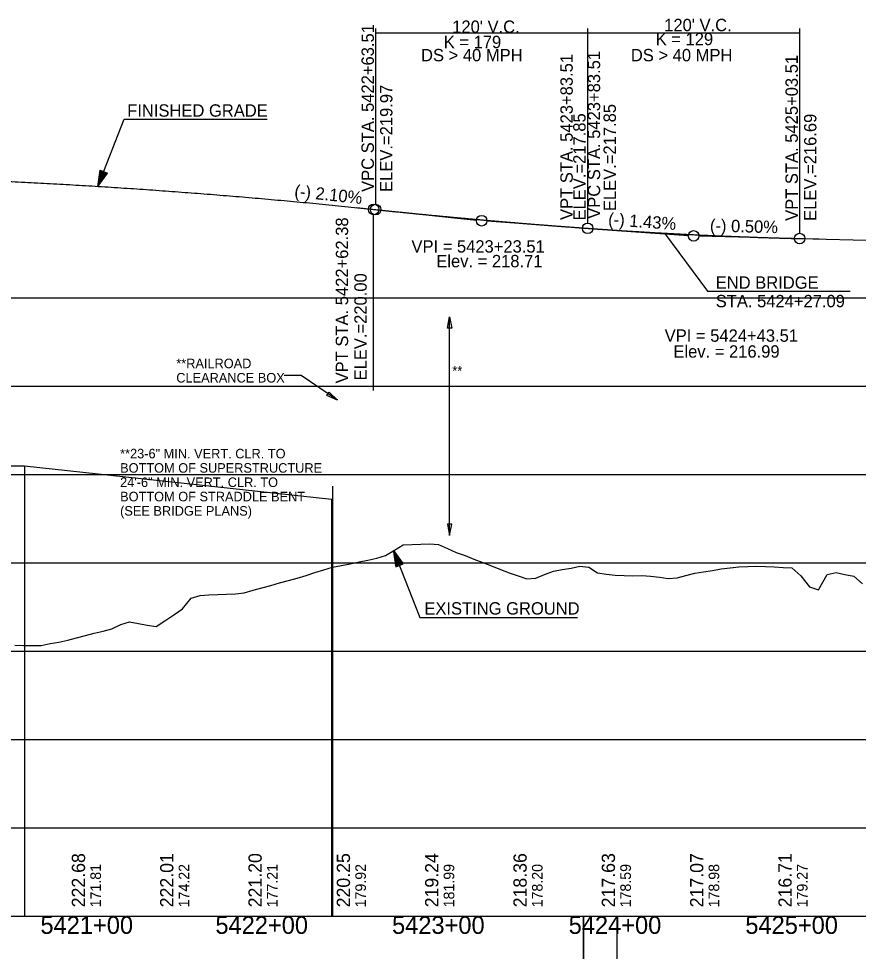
# Model space of a CAD drawing. Extents: x 69 to 2003113, y 512 to 837401.
# Drawn here: x 1885998 to 1886474, y 775969 to 776497 of the extents above; entities that cross this region are included whole.
import ezdxf

# ---------------------------------------------------------------- set-up
doc = ezdxf.new("R2010")
doc.units = 0
for name, color, linetype in [('BR_AUTO DIMENSION', 7, 'Continuous'), ('BR_BORDER LINES', 7, 'Continuous'), ('BR_CENTER LINE BASELINE', 7, 'Continuous'), ('BR_CONCRETE', 7, 'Continuous'), ('BR_GRID DOTS', 7, 'Continuous'), ('BR_GRID LINES', 7, 'Continuous'), ('BR_TEXT', 7, 'Continuous'), ('RD_HC_Points', 7, 'Continuous'), ('RD_PD_ALT1_TrvlWay', 7, 'Continuous'), ('RD_SHT_ID', 7, 'Continuous'), ('RD_SHT_IplotShp', 7, 'Continuous')]:
    doc.layers.add(name, color=color, linetype=linetype)

msp = doc.modelspace()

# ---------------------------------------------------------------- linework, layer by layer
at = {"layer": 'BR_AUTO DIMENSION'}
for p, q in [((1883686.1, 776339.14), (1888825.1, 776339.14)), ((1883686.1, 776289.14), (1888825.1, 776289.14)), ((1885909.13, 776244.04), (1886001.66, 776244.04)), ((1886001.66, 776244.04), (1886001.66, 775989.14)), ((1886001.66, 776244.04), (1886175.45, 776225.04)), ((1883686.1, 776239.14), (1888825.1, 776239.14)), ((1886176.11, 776232.54), (1886176.11, 775989.14)), ((1886175.45, 776225.04), (1886175.45, 775989.14)), ((1886175.45, 776225.04), (1886176.11, 776225.04)), ((1883686.1, 776189.14), (1888825.1, 776189.14)), ((1883686.1, 776139.14), (1888825.1, 776139.14)), ((1883686.1, 776089.14), (1888825.1, 776089.14)), ((1883686.1, 776039.14), (1888825.1, 776039.14)), ((1883636.94, 775989.14), (1888825.1, 775989.14)), ((1886318.05, 775989.14), (1886318.05, 772615.57)), ((1886336.94, 775989.14), (1886336.94, 774739.14))]:
    msp.add_line(p, q, dxfattribs=at)
at = {"layer": 'BR_BORDER LINES'}
for p, q in [((1883686.1, 775989.14), (1889486.1, 775989.14)), ((1886318.05, 774739.14), (1886318.05, 775989.14))]:
    msp.add_line(p, q, dxfattribs=at)
at = {"layer": 'BR_CENTER LINE BASELINE'}
for p, q in [((1886189.84, 776390.11), (1886257.46, 776383.01)), ((1886331.27, 776377.63), (1886263.44, 776382.49)), ((1886336.94, 776377.23), (1886377.46, 776374.33)), ((1886451.43, 776372.33), (1886383.45, 776374.04))]:
    msp.add_line(p, q, dxfattribs=at)
for centre in [(1886260.45, 776382.7), (1886380.45, 776374.11)]:
    msp.add_circle(centre, 3, dxfattribs=at)
at = {"layer": 'BR_GRID DOTS'}
for p, q in [((1886200.45, 776491.5), (1886200.45, 776392)), ((1886320.45, 776491.5), (1886320.45, 776381.41)), ((1886440.45, 776491.5), (1886440.45, 776375.61)), ((1886200.45, 776489), (1886320.45, 776489)), ((1886320.45, 776489), (1886440.45, 776489)), ((1886320.45, 776489), (1886336.94, 776489)), ((1886320.45, 776480.91), (1886320.45, 776381.41)), ((1886199.32, 776286.62), (1886199.32, 776386.12)), ((1885474.32, 776289.12), (1886199.32, 776289.12))]:
    msp.add_line(p, q, dxfattribs=at)
for centre in [(1886199.32, 776389.12), (1886200.45, 776389), (1886320.45, 776378.41), (1886320.45, 776378.41), (1886440.45, 776372.61)]:
    msp.add_circle(centre, 3, dxfattribs=at)
at = {"layer": 'BR_GRID LINES'}
for p, q in [((1886199.32, 776389.12), (1886200.45, 776389)), ((1886320.45, 776378.41), (1886320.45, 776378.41)), ((1886440.45, 776372.61), (1886536.94, 776370.19))]:
    msp.add_line(p, q, dxfattribs=at)
for points in [[(1885474.32, 776392.63), (1885488.82, 776393.99), (1885503.32, 776395.28), (1885517.82, 776396.52), (1885532.32, 776397.7), (1885546.82, 776398.82), (1885561.32, 776399.88), (1885575.82, 776400.88), (1885590.32, 776401.83), (1885604.82, 776402.72), (1885619.32, 776403.55), (1885633.82, 776404.32), (1885648.32, 776405.03), (1885662.82, 776405.69), (1885677.32, 776406.29), (1885691.82, 776406.83), (1885706.32, 776407.31), (1885720.82, 776407.73), (1885735.32, 776408.1), (1885749.82, 776408.41), (1885764.32, 776408.65), (1885778.82, 776408.85), (1885793.32, 776408.98), (1885807.82, 776409.05), (1885822.32, 776409.07), (1885836.82, 776409.03), (1885851.32, 776408.93), (1885865.82, 776408.77), (1885880.32, 776408.56), (1885894.82, 776408.28), (1885909.32, 776407.95), (1885923.82, 776407.56), (1885938.32, 776407.11), (1885952.82, 776406.61), (1885967.32, 776406.04), (1885981.82, 776405.42), (1885996.32, 776404.74), (1886010.82, 776404), (1886025.32, 776403.21), (1886039.82, 776402.35), (1886054.32, 776401.44), (1886068.82, 776400.47), (1886083.32, 776399.44), (1886097.82, 776398.35), (1886112.32, 776397.21), (1886126.82, 776396.01), (1886141.32, 776394.74), (1886155.82, 776393.43), (1886170.32, 776392.05), (1886184.82, 776390.61), (1886199.32, 776389.12)], [(1886200.45, 776389), (1886202.85, 776388.75), (1886205.25, 776388.5), (1886207.65, 776388.25), (1886210.05, 776388.01), (1886212.45, 776387.76), (1886214.85, 776387.52), (1886217.25, 776387.28), (1886219.65, 776387.04), (1886222.05, 776386.8), (1886224.45, 776386.56), (1886226.85, 776386.33), (1886229.25, 776386.09), (1886231.65, 776385.86), (1886234.05, 776385.63), (1886236.45, 776385.4), (1886238.85, 776385.17), (1886241.25, 776384.95), (1886243.65, 776384.72), (1886246.05, 776384.5), (1886248.45, 776384.28), (1886250.85, 776384.06), (1886253.25, 776383.84), (1886255.65, 776383.63), (1886258.05, 776383.41), (1886260.45, 776383.2), (1886262.85, 776382.99), (1886265.25, 776382.78), (1886267.65, 776382.57), (1886270.05, 776382.37), (1886272.45, 776382.16), (1886274.85, 776381.96), (1886277.25, 776381.76), (1886279.65, 776381.56), (1886282.05, 776381.36), (1886284.45, 776381.16), (1886286.85, 776380.97), (1886289.25, 776380.77), (1886291.65, 776380.58), (1886294.05, 776380.39), (1886296.45, 776380.2), (1886298.85, 776380.02), (1886301.25, 776379.83), (1886303.65, 776379.65), (1886306.05, 776379.47), (1886308.45, 776379.29), (1886310.85, 776379.11), (1886313.25, 776378.93), (1886315.65, 776378.75), (1886318.05, 776378.58), (1886320.45, 776378.41)], [(1886320.45, 776378.41), (1886320.78, 776378.38), (1886321.11, 776378.36), (1886321.44, 776378.34), (1886321.77, 776378.31), (1886322.1, 776378.29), (1886322.43, 776378.27), (1886322.76, 776378.24), (1886323.09, 776378.22), (1886323.42, 776378.2), (1886323.75, 776378.17), (1886324.08, 776378.15), (1886324.41, 776378.13), (1886324.74, 776378.1), (1886325.07, 776378.08), (1886325.4, 776378.06), (1886325.73, 776378.03), (1886326.06, 776378.01), (1886326.38, 776377.99), (1886326.71, 776377.97), (1886327.04, 776377.94), (1886327.37, 776377.92), (1886327.7, 776377.9), (1886328.03, 776377.87), (1886328.36, 776377.85), (1886328.69, 776377.83), (1886329.02, 776377.81), (1886329.35, 776377.78), (1886329.68, 776377.76), (1886330.01, 776377.74), (1886330.34, 776377.72), (1886330.67, 776377.7), (1886331, 776377.67), (1886331.33, 776377.65), (1886331.66, 776377.63), (1886331.99, 776377.61), (1886332.32, 776377.58), (1886332.65, 776377.56), (1886332.98, 776377.54), (1886333.31, 776377.52), (1886333.64, 776377.5), (1886333.97, 776377.47), (1886334.3, 776377.45), (1886334.63, 776377.43), (1886334.96, 776377.41), (1886335.29, 776377.39), (1886335.62, 776377.37), (1886335.95, 776377.34), (1886336.28, 776377.32), (1886336.61, 776377.3), (1886336.94, 776377.28)], [(1886336.94, 776377.28), (1886337.25, 776377.26), (1886339.65, 776377.1), (1886342.05, 776376.95), (1886344.45, 776376.8), (1886346.85, 776376.65), (1886349.25, 776376.51), (1886351.65, 776376.36), (1886354.05, 776376.22), (1886356.45, 776376.08), (1886358.85, 776375.94), (1886361.25, 776375.81), (1886363.65, 776375.68), (1886366.05, 776375.55), (1886368.45, 776375.42), (1886370.85, 776375.29), (1886373.25, 776375.17), (1886375.65, 776375.05), (1886378.05, 776374.93), (1886380.45, 776374.81), (1886382.85, 776374.7), (1886385.25, 776374.58), (1886387.65, 776374.47), (1886390.05, 776374.36), (1886392.45, 776374.26), (1886394.85, 776374.15), (1886397.25, 776374.05), (1886399.65, 776373.95), (1886402.05, 776373.86), (1886404.45, 776373.76), (1886406.85, 776373.67), (1886409.25, 776373.58), (1886411.65, 776373.49), (1886414.05, 776373.41), (1886416.45, 776373.32), (1886418.85, 776373.24), (1886421.25, 776373.16), (1886423.65, 776373.08), (1886426.05, 776373.01), (1886428.45, 776372.94), (1886430.85, 776372.87), (1886433.25, 776372.8), (1886435.65, 776372.73), (1886438.05, 776372.67), (1886440.45, 776372.61)]]:
    msp.add_spline(points, degree=3, dxfattribs=at)
at = {"layer": 'BR_TEXT'}
for points in [[(1886186.1, 776188.56), (1886191.1, 776189.59), (1886196.1, 776190.66), (1886201.1, 776191.75), (1886206.1, 776193.28), (1886211.1, 776196.36), (1886216.1, 776199.38), (1886221.1, 776199.52), (1886226.1, 776199.65), (1886231.1, 776199.78), (1886236.1, 776199.5), (1886241.1, 776197.2), (1886246.1, 776195), (1886251.1, 776193.18), (1886256.1, 776191.23), (1886261.1, 776189.28), (1886266.1, 776187.34), (1886271.1, 776185.4), (1886276.1, 776183.47), (1886281.1, 776181.67), (1886286.1, 776180.1), (1886291.1, 776180.37), (1886296.1, 776182.48), (1886301.1, 776184.47), (1886306.1, 776185.26), (1886311.1, 776186.08), (1886316.1, 776187.16), (1886321.1, 776186.72), (1886326.1, 776183.45), (1886331.1, 776182.65), (1886336.1, 776182.16), (1886341.1, 776181.88), (1886346.1, 776181.77), (1886351.1, 776181.96), (1886356.1, 776181.48), (1886361.1, 776181.05), (1886366.1, 776180.15), (1886371.1, 776180.64), (1886376.1, 776182.01), (1886381.1, 776183.19), (1886386.1, 776183.92), (1886391.1, 776184.72), (1886396.1, 776185.75), (1886401.1, 776186.31), (1886406.1, 776186.9), (1886411.1, 776186.96), (1886416.1, 776187.27), (1886421.1, 776187.07), (1886426.1, 776186.77), (1886431.1, 776186.54), (1886436.1, 776186.25), (1886441.1, 776181.81), (1886446.1, 776175.6), (1886451.1, 776173.73), (1886456.1, 776182.56), (1886461.1, 776183.66), (1886466.1, 776182.57), (1886471.1, 776181.65), (1886476.1, 776177.21)], [(1885996.1, 776142.58), (1886001.1, 776142.34), (1886006.1, 776142.25), (1886011.1, 776142.4), (1886016.1, 776143.39), (1886021.1, 776144.19), (1886026.1, 776145.43), (1886031.1, 776146.68), (1886036.1, 776147.97), (1886041.1, 776149.26), (1886046.1, 776150.52), (1886051.1, 776151.81), (1886056.1, 776154.12), (1886061.1, 776155.65), (1886066.1, 776154.74), (1886071.1, 776153.88), (1886076.1, 776153.07), (1886081.1, 776156.28), (1886086.1, 776159.69), (1886091.1, 776163.15), (1886096.1, 776169.02), (1886101.1, 776170.54), (1886106.1, 776170.92), (1886111.1, 776171.12), (1886116.1, 776171.32), (1886121.1, 776171.52), (1886126.1, 776172.14), (1886131.1, 776173.56), (1886136.1, 776174.98), (1886141.1, 776176.36), (1886146.1, 776177.72), (1886151.1, 776179.09), (1886156.1, 776180.48), (1886161.1, 776182), (1886166.1, 776183.59), (1886171.1, 776185.19), (1886176.1, 776186.58), (1886181.1, 776187.53), (1886186.1, 776188.56)]]:
    msp.add_lwpolyline(points, dxfattribs=at)
at = {"layer": 'RD_PD_ALT1_TrvlWay'}
for p, q in [((1886043.2, 776402.14), (1886058.16, 776440.1)), ((1886058.16, 776440.1), (1886138.94, 776440.1)), ((1886043.2, 776402.14), (1886044.41, 776411.34)), ((1886046.5, 776410.52), (1886043.2, 776402.14)), ((1886044.41, 776411.34), (1886048.6, 776409.69)), ((1886043.2, 776402.14), (1886048.6, 776409.69)), ((1886364.03, 776375.66), (1886388.31, 776342.87)), ((1886388.31, 776342.87), (1886469.09, 776342.87)), ((1886242.29, 776204.53), (1886242.29, 776328.4)), ((1886158.26, 776295.16), (1886148.71, 776295.16)), ((1886178.79, 776281.06), (1886158.26, 776295.16)), ((1886210.59, 776196.05), (1886225.55, 776158.09)), ((1886213.89, 776187.68), (1886210.59, 776196.05)), ((1886210.59, 776196.05), (1886215.99, 776188.5)), ((1886210.59, 776196.05), (1886211.8, 776186.85)), ((1886211.8, 776186.85), (1886215.99, 776188.5)), ((1886225.55, 776158.09), (1886314.74, 776158.09))]:
    msp.add_line(p, q, dxfattribs=at)
for points in [[(1886046.4, 776410.44), (1886043.33, 776402.64), (1886046.37, 776410.51), (1886043.4, 776403.03), (1886046.27, 776410.51), (1886043.43, 776403.3), (1886046.16, 776410.53), (1886043.46, 776403.63), (1886046.08, 776410.58), (1886043.53, 776404.12), (1886045.96, 776410.65), (1886043.62, 776404.65), (1886045.85, 776410.66), (1886043.68, 776405.05), (1886045.77, 776410.71), (1886043.74, 776405.5), (1886045.66, 776410.69), (1886043.79, 776405.9), (1886045.6, 776410.79), (1886043.83, 776406.25), (1886045.47, 776410.81), (1886043.88, 776406.75), (1886045.37, 776410.86), (1886044, 776407.34), (1886045.27, 776410.92), (1886044, 776407.76), (1886045.17, 776410.96), (1886044.09, 776408.39), (1886045.05, 776410.97), (1886044.19, 776408.89), (1886044.95, 776411.07), (1886044.24, 776409.33), (1886044.85, 776411.07), (1886044.28, 776409.73), (1886044.76, 776411.16), (1886044.35, 776410.22), (1886044.65, 776411.13), (1886044.43, 776410.77), (1886044.53, 776411.13)], [(1886043.48, 776402.66), (1886046.52, 776410.39), (1886043.64, 776402.92), (1886046.63, 776410.35), (1886043.79, 776403.16), (1886046.71, 776410.36), (1886043.97, 776403.37), (1886046.77, 776410.31), (1886044.18, 776403.63), (1886046.86, 776410.29), (1886044.36, 776403.88), (1886046.93, 776410.27), (1886044.57, 776404.17), (1886047.03, 776410.25), (1886044.82, 776404.54), (1886047.14, 776410.19), (1886045.02, 776404.86), (1886047.22, 776410.19), (1886045.25, 776405.19), (1886047.3, 776410.14), (1886045.49, 776405.49), (1886047.39, 776410.11), (1886045.73, 776405.84), (1886047.44, 776410.03), (1886046.05, 776406.29), (1886047.54, 776410.03), (1886046.28, 776406.58), (1886047.62, 776410.04), (1886046.57, 776406.97), (1886047.7, 776409.97), (1886046.81, 776407.37), (1886047.79, 776409.91), (1886047.04, 776407.68), (1886047.88, 776409.82), (1886047.29, 776407.97), (1886047.95, 776409.79), (1886047.57, 776408.43), (1886048.09, 776409.81), (1886047.76, 776408.7), (1886048.23, 776409.75), (1886047.94, 776408.87), (1886048.34, 776409.61), (1886048.46, 776409.67), (1886048.3, 776409.63)], [(1886213.79, 776187.76), (1886210.72, 776195.55), (1886213.76, 776187.68), (1886210.79, 776195.16), (1886213.66, 776187.68), (1886210.82, 776194.89), (1886213.55, 776187.66), (1886210.85, 776194.56), (1886213.47, 776187.61), (1886210.92, 776194.07), (1886213.36, 776187.54), (1886211.01, 776193.54), (1886213.24, 776187.54), (1886211.07, 776193.15), (1886213.16, 776187.49), (1886211.13, 776192.69), (1886213.05, 776187.5), (1886211.18, 776192.29), (1886212.99, 776187.4), (1886211.22, 776191.95), (1886212.86, 776187.39), (1886211.28, 776191.45), (1886212.76, 776187.33), (1886211.39, 776190.85), (1886212.66, 776187.27), (1886211.4, 776190.43), (1886212.56, 776187.23), (1886211.48, 776189.81), (1886212.44, 776187.22), (1886211.58, 776189.31), (1886212.34, 776187.12), (1886211.63, 776188.87), (1886212.24, 776187.12), (1886211.67, 776188.46), (1886212.16, 776187.03), (1886211.75, 776187.97), (1886212.04, 776187.07), (1886211.82, 776187.42), (1886211.92, 776187.06)], [(1886210.87, 776195.53), (1886213.91, 776187.8), (1886211.03, 776195.27), (1886214.02, 776187.84), (1886211.18, 776195.03), (1886214.1, 776187.84), (1886211.37, 776194.83), (1886214.16, 776187.88), (1886211.57, 776194.56), (1886214.26, 776187.9), (1886211.75, 776194.31), (1886214.33, 776187.93), (1886211.96, 776194.02), (1886214.42, 776187.94), (1886212.21, 776193.66), (1886214.53, 776188.01), (1886212.41, 776193.34), (1886214.62, 776188), (1886212.64, 776193.01), (1886214.7, 776188.05), (1886212.88, 776192.7), (1886214.78, 776188.09), (1886213.12, 776192.35), (1886214.83, 776188.17), (1886213.44, 776191.9), (1886214.93, 776188.16), (1886213.67, 776191.61), (1886215.01, 776188.16), (1886213.97, 776191.23), (1886215.09, 776188.23), (1886214.21, 776190.82), (1886215.18, 776188.28), (1886214.43, 776190.51), (1886215.27, 776188.38), (1886214.68, 776190.23), (1886215.34, 776188.4), (1886214.96, 776189.76), (1886215.49, 776188.38), (1886215.15, 776189.49), (1886215.62, 776188.44), (1886215.34, 776189.32), (1886215.73, 776188.58), (1886215.85, 776188.53), (1886215.69, 776188.57)]]:
    msp.add_lwpolyline(points, dxfattribs=at)
for points in [[(1886241.04, 776321.9), (1886242.29, 776328.4), (1886243.54, 776321.9)], [(1886174.14, 776285.77), (1886178.79, 776281.06), (1886172.73, 776283.71)], [(1886241.04, 776211.03), (1886242.29, 776204.53), (1886243.54, 776211.03)]]:
    msp.add_lwpolyline(points, close=True, dxfattribs=at)

# ---------------------------------------------------------------- texts
at = {"layer": 'BR_CENTER LINE BASELINE'}
for s, rotation, p in [('(-) 2.10%', 354.0059, (1886154.2, 776396.14)), ('(-) 1.43%', 355.9066, (1886331.91, 776380.18)), ('(-) 0.50%', 358.564, (1886389.62, 776376.58))]:
    msp.add_text(s, height=7, rotation=rotation, dxfattribs=at).set_placement(p)
at = {"layer": 'BR_CONCRETE'}
for s, height, p in [('VPC STA. 5422+63.51 ', 7, (1886199.45, 776399)), ('VPT STA. 5423+83.51 ', 7, (1886312.02, 776383.13)), ('VPC STA. 5423+83.51 ', 7, (1886327.52, 776383.79)), ('VPT STA. 5425+03.51 ', 7, (1886439.45, 776382.61)), ('ELEV.=219.97', 7, (1886209.95, 776399)), ('ELEV.=217.85', 7, (1886336.44, 776388.12)), ('ELEV.=217.85', 7, (1886319.28, 776382.85)), ('ELEV.=216.69', 7, (1886449.95, 776382.61)), ('VPT STA. 5422+62.38 ', 7, (1886184.87, 776290.65)), ('ELEV.=220.00', 7, (1886195.37, 776292.33)), ('171.81', 6, (1886044.94, 775994.14)), ('174.22', 6, (1886094.94, 775994.14)), ('177.21', 6, (1886144.94, 775994.14)), ('179.92', 6, (1886194.94, 775994.14)), ('181.99', 6, (1886244.94, 775994.14)), ('178.20', 6, (1886294.94, 775994.14)), ('178.59', 6, (1886344.94, 775994.14)), ('178.98', 6, (1886394.94, 775994.14)), ('179.27', 6, (1886444.94, 775994.14))]:
    msp.add_text(s, height=height, rotation=90, dxfattribs=at).set_placement(p)
at = {"layer": 'BR_GRID DOTS'}
for s, p in [("120' V.C.", (1886243.8, 776489)), ("120' V.C.", (1886363.8, 776489.95)), ('K = 179', (1886238.98, 776480.34)), ('K = 129', (1886358.98, 776482.04)), ('DS > 40 MPH', (1886226.14, 776472.91)), ('DS > 40 MPH', (1886344.92, 776472.91))]:
    msp.add_text(s, height=7, dxfattribs=at).set_placement(p)
at = {"layer": 'RD_HC_Points'}
for s, p in [('222.68', (1886035.94, 775994.14)), ('222.01', (1886085.94, 775994.14)), ('221.20', (1886135.94, 775994.14)), ('220.25', (1886185.94, 775994.14)), ('219.24', (1886235.94, 775994.14)), ('218.36', (1886285.94, 775994.14)), ('217.63', (1886335.94, 775994.14)), ('217.07', (1886385.94, 775994.14)), ('216.71', (1886435.94, 775994.14))]:
    msp.add_text(s, height=7.5, rotation=90, dxfattribs=at).set_placement(p)
at = {"layer": 'RD_PD_ALT1_TrvlWay'}
for s, p in [('FINISHED GRADE', (1886059.8, 776441.57)), ('EXISTING GROUND', (1886228.02, 776159.82))]:
    msp.add_text(s, height=7, dxfattribs=at).set_placement(p)
for s, p in [('**RAILROAD', (1886087.58, 776299.23)), ('**', (1886243.87, 776295.04)), ('CLEARANCE BOX', (1886087.58, 776291.13)), ('**23-6" MIN. VERT. CLR. TO ', (1886055.79, 776248.21)), ('BOTTOM OF SUPERSTRUCTURE', (1886055.79, 776240.11)), ('24\'-6" MIN. VERT. CLR. TO ', (1886055.79, 776232.01)), ('BOTTOM OF STRADDLE BENT', (1886055.79, 776223.91)), ('(SEE BRIDGE PLANS)', (1886055.79, 776215.81))]:
    msp.add_text(s, height=5.4, rotation=360, dxfattribs=at).set_placement(p)
at = {"layer": 'RD_SHT_ID'}
for s, p in [('5421+00', (1886010.68, 775979.14)), ('5422+00', (1886109.72, 775979.14)), ('5423+00', (1886209.72, 775979.14)), ('5424+00', (1886309.72, 775979.14)), ('5425+00', (1886409.72, 775979.14))]:
    msp.add_text(s, height=10, dxfattribs=at).set_placement(p)
at = {"layer": 'RD_SHT_IplotShp'}
for s, p in [('VPI = 5423+23.51', (1886220.71, 776364.66)), ('Elev. = 218.71', (1886234.79, 776356.37)), ('END BRIDGE', (1886392.96, 776344.22)), ('STA. 5424+27.09', (1886392.96, 776333.72)), ('VPI = 5424+43.51', (1886364.08, 776314.21)), ('Elev. = 216.99', (1886369.01, 776305.21))]:
    msp.add_text(s, height=7, dxfattribs=at).set_placement(p)

doc.saveas('drawing.dxf')
